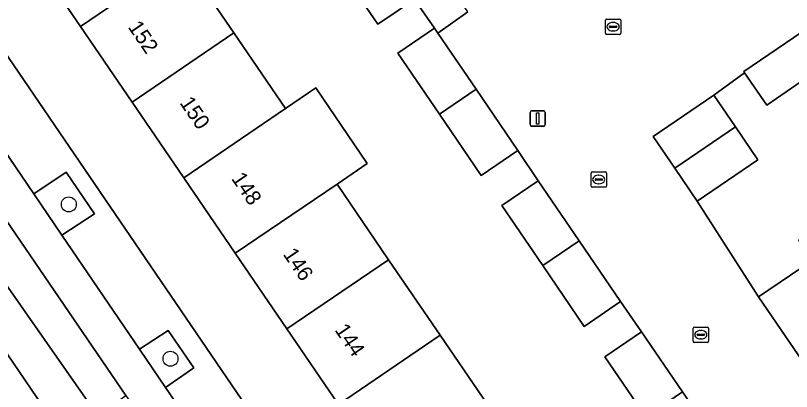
# Model space of a CAD drawing. Extents: x 160030 to 160839, y 385325 to 386450.
# Drawn here: x 160149 to 160199.8, y 385944.4 to 385969.1 of the extents above; entities that cross this region are included whole.
import ezdxf

# ---------------------------------------------------------------- set-up
doc = ezdxf.new("R2010")
doc.units = 0
for name, color, linetype in [('IMGEO_Berm_groen', 7, 'Continuous'), ('IMGEO_Boom', 7, 'Continuous'), ('IMGEO_Erf', 7, 'Continuous'), ('IMGEO_Fietspad_gesloten', 7, 'Continuous'), ('IMGEO_Groenvoorziening', 7, 'Continuous'), ('IMGEO_Kolk', 7, 'Continuous'), ('IMGEO_Lichtmast', 7, 'Continuous'), ('IMGEO_Pand', 7, 'Continuous'), ('IMGEO_Pand_nummerreeks', 7, 'Continuous'), ('IMGEO_Parkeervlak_open', 7, 'Continuous'), ('IMGEO_Rijbaan_lokaal_gesloten', 7, 'Continuous'), ('IMGEO_Rijbaan_lokaal_open', 7, 'Continuous'), ('IMGEO_Voetpad_open', 7, 'Continuous')]:
    doc.layers.add(name, color=color, linetype=linetype)

msp = doc.modelspace()

# ---------------------------------------------------------------- linework, layer by layer
at = {"layer": 'IMGEO_Berm_groen'}
msp.add_lwpolyline([(160144.062, 385957.793), (160147.921, 385952.147), (160153.786, 385943.798), (160154.411, 385942.868), (160156.275, 385944.192), (160144.649, 385961.187)], dxfattribs=at)
at = {"layer": 'IMGEO_Boom'}
for centre in [(160152.532, 385956.712), (160159.188, 385946.596)]:
    msp.add_circle(centre, 0.489, dxfattribs=at)
at = {"layer": 'IMGEO_Erf'}
for points in [[(160124.511, 386001.685), (160125.658, 386000), (160176.803, 385924.884)], [(160178.318, 385924.594), (160197.396, 385937.571), (160196.216, 385939.303), (160192.853, 385937.011), (160191.14, 385939.525), (160194.502, 385941.817), (160192.722, 385944.429), (160190.317, 385942.789), (160187.631, 385946.73), (160190.036, 385948.37), (160188.659, 385950.341), (160186.277, 385948.718), (160183.559, 385952.705), (160180.878, 385956.638), (160183.26, 385958.261), (160181.93, 385960.252), (160179.53, 385958.617), (160176.802, 385962.62), (160174.071, 385966.627), (160176.47, 385968.262), (160175.171, 385970.168), (160172.772, 385968.533), (160170.043, 385972.536), (160167.312, 385976.543)], [(160159.953, 385972.919), (160163.332, 385967.961), (160166.712, 385963.003), (160168.694, 385964.354), (160172.073, 385959.396), (160170.091, 385958.045), (160173.47, 385953.087), (160176.85, 385948.13), (160180.229, 385943.171), (160183.608, 385938.214), (160185.442, 385939.464), (160188.889, 385934.408), (160187.055, 385933.158), (160180.395, 385928.618), (160176.949, 385933.674), (160173.57, 385938.631), (160170.19, 385943.59), (160166.811, 385948.548), (160163.432, 385953.505), (160160.052, 385958.463), (160156.673, 385963.421), (160153.293, 385968.379), (160149.914, 385973.337)], [(160202.026, 385965.844), (160198.223, 385963.221), (160196.78, 385965.338), (160194.754, 385963.871), (160196.172, 385961.791), (160197.65, 385959.623), (160193.682, 385956.919), (160197.695, 385950.657), (160201.194, 385953.043)]]:
    msp.add_lwpolyline(points, dxfattribs=at)
at = {"layer": 'IMGEO_Fietspad_gesloten'}
msp.add_lwpolyline([(160144.649, 385961.187), (160156.275, 385944.192), (160156.952, 385943.201), (160168.644, 385926.099), (160170.472, 385927.74), (160169.812, 385928.661), (160165.492, 385934.989), (160163.973, 385937.215), (160158.87, 385944.704), (160157.155, 385947.225), (160152.08, 385954.685), (160150.233, 385957.4), (160145.465, 385964.411), (160143.914, 385966.694), (160138.5, 385974.658), (160136.979, 385976.896), (160131.713, 385984.643), (160130.172, 385986.909), (160124.758, 385994.871), (160123.429, 385996.826), (160122.081, 385998.808), (160113.781, 386010.901)], dxfattribs=at)
at = {"layer": 'IMGEO_Groenvoorziening'}
for points in [[(160152.349, 385958.836), (160150.233, 385957.4), (160152.08, 385954.685), (160154.206, 385956.098)], [(160159.032, 385948.443), (160157.155, 385947.225), (160158.87, 385944.704), (160160.723, 385946.002)]]:
    msp.add_lwpolyline(points, close=True, dxfattribs=at)
at = {"layer": 'IMGEO_Kolk'}
for p, q in [((160187.666, 385967.933), (160187.666, 385968.785)), ((160187.741, 385968.859), (160188.593, 385968.859)), ((160188.154, 385968.639), (160188.179, 385968.639)), ((160188.667, 385968.785), (160188.667, 385967.933)), ((160187.925, 385968.353), (160187.925, 385968.365)), ((160188.363, 385968.316), (160187.965, 385968.316)), ((160187.968, 385968.402), (160188.366, 385968.402)), ((160188.177, 385968.079), (160188.152, 385968.079)), ((160188.409, 385968.365), (160188.409, 385968.353)), ((160188.593, 385967.859), (160187.741, 385967.859)), ((160186.725, 385957.916), (160186.725, 385958.768)), ((160186.8, 385958.842), (160187.652, 385958.842)), ((160186.984, 385958.336), (160186.984, 385958.348)), ((160187.027, 385958.385), (160187.425, 385958.385)), ((160187.213, 385958.622), (160187.238, 385958.622)), ((160187.468, 385958.348), (160187.468, 385958.336)), ((160187.726, 385958.768), (160187.726, 385957.916)), ((160187.652, 385957.842), (160186.8, 385957.842)), ((160187.422, 385958.299), (160187.024, 385958.299)), ((160187.236, 385958.062), (160187.211, 385958.062)), ((160193.412, 385947.744), (160193.412, 385948.596)), ((160193.487, 385948.67), (160194.339, 385948.67)), ((160193.714, 385948.213), (160194.112, 385948.213)), ((160193.9, 385948.45), (160193.925, 385948.45)), ((160194.413, 385948.596), (160194.413, 385947.744)), ((160193.671, 385948.164), (160193.671, 385948.176)), ((160194.109, 385948.127), (160193.711, 385948.127)), ((160193.923, 385947.89), (160193.898, 385947.89)), ((160194.155, 385948.176), (160194.155, 385948.164)), ((160194.339, 385947.67), (160193.487, 385947.67))]:
    msp.add_line(p, q, dxfattribs=at)
for points in [[(160187.666, 385967.933), (160187.666, 385968.785)], [(160187.741, 385968.859), (160188.593, 385968.859)], [(160188.667, 385968.785), (160188.667, 385967.933)], [(160188.593, 385967.859), (160187.741, 385967.859)], [(160186.725, 385957.916), (160186.725, 385958.768)], [(160186.8, 385958.842), (160187.652, 385958.842)], [(160187.726, 385958.768), (160187.726, 385957.916)], [(160187.652, 385957.842), (160186.8, 385957.842)], [(160193.412, 385947.744), (160193.412, 385948.596)], [(160193.487, 385948.67), (160194.339, 385948.67)], [(160194.413, 385948.596), (160194.413, 385947.744)], [(160194.339, 385947.67), (160193.487, 385947.67)]]:
    msp.add_lwpolyline(points, dxfattribs=at)
for centre, radius, start, end in [((160187.743, 385968.783), 0.0765, 91.552, 178.448), ((160187.743, 385968.783), 0.0765, 91.552, 178.448), ((160188.591, 385968.783), 0.0765, 1.552, 88.448), ((160188.591, 385968.783), 0.0765, 1.552, 88.448), ((160187.965, 385968.362), 0.0403, 85.8775, 175.7526), ((160187.962, 385968.352), 0.0366, 178.938, 274.7102), ((160188.366, 385968.359), 0.043, 264.8664, 352.4533), ((160188.37, 385968.364), 0.0386, 1.7309, 96.639), ((160187.743, 385967.935), 0.0765, 181.552, 268.448), ((160187.743, 385967.935), 0.0765, 181.552, 268.448), ((160188.591, 385967.935), 0.0765, 271.552, 358.448), ((160188.591, 385967.935), 0.0765, 271.552, 358.448), ((160186.802, 385958.766), 0.0765, 91.552, 178.448), ((160186.802, 385958.766), 0.0765, 91.552, 178.448), ((160187.024, 385958.345), 0.0403, 85.8775, 175.7526), ((160187.429, 385958.347), 0.0386, 1.7309, 96.639), ((160187.65, 385958.766), 0.0765, 1.552, 88.448), ((160187.65, 385958.766), 0.0765, 1.552, 88.448), ((160186.802, 385957.918), 0.0765, 181.552, 268.448), ((160186.802, 385957.918), 0.0765, 181.552, 268.448), ((160187.021, 385958.335), 0.0366, 178.938, 274.7102), ((160187.425, 385958.342), 0.043, 264.8664, 352.4533), ((160187.65, 385957.918), 0.0765, 271.552, 358.448), ((160187.65, 385957.918), 0.0765, 271.552, 358.448), ((160193.489, 385948.594), 0.0765, 91.552, 178.448), ((160193.489, 385948.594), 0.0765, 91.552, 178.448), ((160193.711, 385948.173), 0.0403, 85.8775, 175.7526), ((160194.116, 385948.175), 0.0386, 1.7309, 96.639), ((160194.337, 385948.594), 0.0765, 1.552, 88.448), ((160194.337, 385948.594), 0.0765, 1.552, 88.448), ((160193.489, 385947.746), 0.0765, 181.552, 268.448), ((160193.489, 385947.746), 0.0765, 181.552, 268.448), ((160193.708, 385948.163), 0.0366, 178.938, 274.7102), ((160194.112, 385948.17), 0.043, 264.8664, 352.4533), ((160194.337, 385947.746), 0.0765, 271.552, 358.448), ((160194.337, 385947.746), 0.0765, 271.552, 358.448)]:
    msp.add_arc(centre, radius, start, end, dxfattribs=at)
for centre, major_axis, ratio, start_param, end_param in [((160188.153, 385968.359), (-0.387, 0.002), 0.722429, 4.712389, 7.853982), ((160188.178, 385968.359), (-0.39, 0.002), 0.717154, 1.570796, 4.712389), ((160187.212, 385958.342), (-0.387, 0.002), 0.722429, 4.712389, 7.853982), ((160187.237, 385958.342), (-0.39, 0.002), 0.717154, 1.570796, 4.712389), ((160193.899, 385948.17), (-0.387, 0.002), 0.722429, 4.712389, 7.853982), ((160193.924, 385948.17), (-0.39, 0.002), 0.717154, 1.570796, 4.712389)]:
    msp.add_ellipse(centre, major_axis=major_axis, ratio=ratio, start_param=start_param, end_param=end_param, dxfattribs=at)
at = {"layer": 'IMGEO_Lichtmast'}
for p, q in [((160182.732, 385961.947), (160182.732, 385962.747)), ((160182.732, 385962.747), (160182.732, 385961.947)), ((160182.832, 385962.847), (160183.622, 385962.847)), ((160183.622, 385962.847), (160182.832, 385962.847)), ((160183.722, 385962.747), (160183.722, 385961.947)), ((160183.722, 385961.947), (160183.722, 385962.747)), ((160183.622, 385961.847), (160182.832, 385961.847)), ((160182.832, 385961.847), (160183.622, 385961.847))]:
    msp.add_line(p, q, dxfattribs=at)
msp.add_lwpolyline([(160183.152, 385962.722), (160183.302, 385962.722), (160183.302, 385961.972), (160183.152, 385961.972), (160183.152, 385962.722)], dxfattribs=at)
for centre, start, end in [((160182.832, 385962.747), 90, 180), ((160182.832, 385962.747), 90, 180), ((160183.622, 385962.747), 0, 90), ((160183.622, 385962.747), 360, 90), ((160182.832, 385961.947), 180, 270), ((160182.832, 385961.947), 180, 270), ((160183.622, 385961.947), 270, 0), ((160183.622, 385961.947), 270, 0)]:
    msp.add_arc(centre, 0.1, start, end, dxfattribs=at)
at = {"layer": 'IMGEO_Pand'}
for points in [[(160159.953, 385972.919), (160156.574, 385977.876), (160149.914, 385973.337), (160153.293, 385968.379)], [(160172.442, 385974.171), (160170.043, 385972.536), (160172.772, 385968.533), (160175.171, 385970.168)], [(160153.293, 385968.379), (160156.673, 385963.421), (160163.332, 385967.961), (160159.953, 385972.919)], [(160176.694, 385967.933), (160176.47, 385968.262), (160174.071, 385966.627), (160176.802, 385962.62), (160179.201, 385964.256)], [(160202.026, 385965.844), (160200.536, 385968.03), (160196.718, 385965.429), (160196.78, 385965.338), (160198.223, 385963.221)], [(160166.712, 385963.003), (160163.332, 385967.961), (160156.673, 385963.421), (160160.052, 385958.463)], [(160170.091, 385958.045), (160172.073, 385959.396), (160168.694, 385964.354), (160166.712, 385963.003), (160160.052, 385958.463), (160163.432, 385953.505)], [(160179.201, 385964.256), (160176.802, 385962.62), (160179.53, 385958.617), (160181.93, 385960.252)], [(160196.172, 385961.791), (160194.754, 385963.871), (160190.786, 385961.165), (160192.204, 385959.086)], [(160196.172, 385961.791), (160192.204, 385959.086), (160193.682, 385956.919), (160197.65, 385959.623)], [(160163.432, 385953.505), (160166.811, 385948.548), (160173.47, 385953.087), (160170.091, 385958.045)], [(160183.26, 385958.261), (160180.878, 385956.638), (160183.559, 385952.705), (160185.941, 385954.328)], [(160202.785, 385954.127), (160201.893, 385955.435), (160200.303, 385954.351), (160201.194, 385953.043), (160197.695, 385950.657), (160201.466, 385945.126), (160206.556, 385948.596)], [(160185.941, 385954.328), (160183.559, 385952.705), (160186.277, 385948.718), (160188.659, 385950.341)], [(160176.85, 385948.13), (160173.47, 385953.087), (160166.811, 385948.548), (160170.19, 385943.59)], [(160190.036, 385948.37), (160187.631, 385946.73), (160190.317, 385942.789), (160192.722, 385944.429)], [(160180.229, 385943.171), (160176.85, 385948.13), (160170.19, 385943.59), (160173.57, 385938.631)]]:
    msp.add_lwpolyline(points, close=True, dxfattribs=at)
at = {"layer": 'IMGEO_Parkeervlak_open'}
for points in [[(160139.879, 385959.599), (160145.423, 385951.415), (160163.163, 385925.317)], [(160153.786, 385943.798), (160147.921, 385952.147), (160144.062, 385957.793)]]:
    msp.add_lwpolyline(points, dxfattribs=at)
at = {"layer": 'IMGEO_Rijbaan_lokaal_gesloten'}
msp.add_lwpolyline([(160072.038, 386050.801), (160160.544, 385920.543), (160164.54, 385923.307), (160163.163, 385925.317), (160145.423, 385951.415), (160139.879, 385959.599), (160139.703, 385959.857), (160139.542, 385960.093), (160138.154, 385962.123), (160138.083, 385962.227), (160137.984, 385962.372), (160137.915, 385962.473), (160133.356, 385969.12), (160120.595, 385987.575), (160116.757, 385993.446), (160106.939, 386007.869), (160103.17, 386013.216)], dxfattribs=at)
at = {"layer": 'IMGEO_Rijbaan_lokaal_open'}
for points in [[(160178.659, 385969.33), (160176.694, 385967.933), (160179.201, 385964.256), (160181.93, 385960.252), (160183.26, 385958.261), (160185.941, 385954.328), (160188.659, 385950.341), (160190.036, 385948.37), (160192.722, 385944.429), (160194.502, 385941.817), (160196.216, 385939.303), (160197.396, 385937.571), (160198.726, 385938.499), (160202.379, 385941.045)], [(160201.466, 385945.126), (160197.695, 385950.657), (160193.682, 385956.919), (160192.204, 385959.086), (160190.786, 385961.165), (160194.754, 385963.871), (160196.78, 385965.338), (160196.718, 385965.429), (160200.536, 385968.03)]]:
    msp.add_lwpolyline(points, dxfattribs=at)
at = {"layer": 'IMGEO_Voetpad_open'}
for points in [[(160176.803, 385924.884), (160125.658, 386000)], [(160145.465, 385964.411), (160150.233, 385957.4), (160152.349, 385958.836), (160154.206, 385956.098), (160152.08, 385954.685), (160157.155, 385947.225), (160159.032, 385948.443), (160160.723, 385946.002), (160158.87, 385944.704), (160163.973, 385937.215), (160165.985, 385938.649), (160167.643, 385936.37), (160165.492, 385934.989), (160169.812, 385928.661), (160170.472, 385927.74), (160172.387, 385929.067), (160174.149, 385926.531), (160172.174, 385925.159), (160174.467, 385921.813), (160175.111, 385920.946)]]:
    msp.add_lwpolyline(points, dxfattribs=at)
msp.add_lwpolyline([(160174.68, 385975.189), (160173.837, 385974.627), (160171.159, 385978.645), (160169.738, 385980.746), (160169.007, 385980.255), (160168.519, 385979.928), (160169.711, 385978.178), (160172.442, 385974.171), (160175.171, 385970.168), (160176.47, 385968.262), (160176.694, 385967.933), (160178.659, 385969.33), (160175.39, 385974.124)], close=True, dxfattribs=at)

# ---------------------------------------------------------------- texts
at = {"layer": 'IMGEO_Pand_nummerreeks'}
for s, p in [('152', (160156.369, 385968.338)), ('150', (160159.756, 385963.368)), ('148', (160163.14, 385958.403)), ('146', (160166.523, 385953.442)), ('144', (160169.907, 385948.477))]:
    msp.add_text(s, height=1, rotation=304.2816, dxfattribs=at).set_placement(p)

doc.saveas('drawing.dxf')
